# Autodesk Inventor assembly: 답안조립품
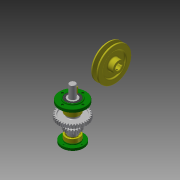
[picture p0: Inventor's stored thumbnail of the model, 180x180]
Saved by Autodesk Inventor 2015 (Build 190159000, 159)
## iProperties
Created: 2016-10
Part Number: 답안조립품
Document SubType Name: Assembly
Designer: Admin
Author: Admin
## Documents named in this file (12)
- C:\Users\Admin\Desktop\461007V1015\답안조립품.iam
- C:\Users\Admin\Desktop\461007V1015\본체.ipt
- C:\Users\Admin\Desktop\461007V1015\앞커버.ipt
- C:\Users\Admin\Desktop\461007V1015\베어링 6203.ipt
- C:\Users\Admin\Desktop\461007V1015\뒤커버.ipt
- C:\Users\Admin\Desktop\461007V1015\축.ipt
- C:\Users\Admin\Desktop\461007V1015\키 - 6 x 6 x 22.ipt
- C:\Users\Admin\Desktop\461007V1015\스퍼기어.ipt
- C:\Users\Admin\Desktop\461007V1015\오일씰 28 40 8.ipt
- C:\Users\Admin\Desktop\461007V1015\부시.ipt
- C:\Users\Admin\Desktop\461007V1015\키 - 5 x 5 x 18.ipt
- C:\Users\Admin\Desktop\461007V1015\V-벨트풀리.ipt
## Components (1 placed, 1 different names)
1. V-벨트풀리:1
